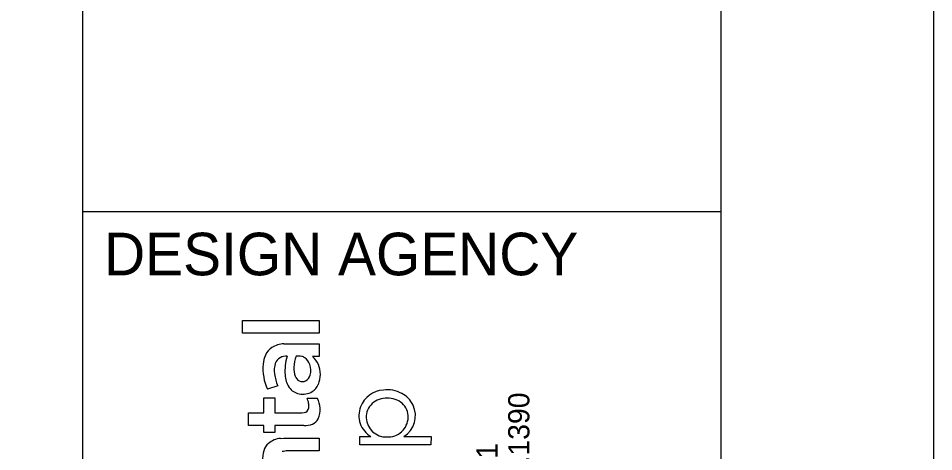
# Model space of a CAD drawing. Extents: x -0.4 to 34, y 0 to 22.
# Drawn here: x 31.848 to 34, y 3.936 to 4.953 of the extents above; entities that cross this region are included whole.
import ezdxf

# ---------------------------------------------------------------- set-up
doc = ezdxf.new("R2010")
doc.units = 0
for name, color, linetype in [('SH_Border', 7, 'Continuous'), ('SH_Cut_Line', 7, 'Continuous'), ('SH_Data', 7, 'Continuous')]:
    doc.layers.add(name, color=color, linetype=linetype)

msp = doc.modelspace()

# ---------------------------------------------------------------- linework, layer by layer
at = {"layer": 'SH_Border'}
for p, q in [((32, 0.5), (32, 21.5)), ((32, 4.5), (33.5, 4.5))]:
    msp.add_line(p, q, dxfattribs=at)
msp.add_lwpolyline([(1.5, 21.5), (33.5, 21.5), (33.5, 0.5), (1.5, 0.5)], close=True, dxfattribs=at)
at = {"layer": 'SH_Cut_Line'}
msp.add_lwpolyline([(0, 0), (34, 0), (34, 22), (0, 22)], close=True, dxfattribs=at)
at = {"layer": 'SH_Data'}
for p, q in [((32.3756, 4.2141), (32.3756, 4.244)), ((32.3756, 4.244), (32.5557, 4.244)), ((32.5557, 4.244), (32.5557, 4.2141)), ((32.5557, 4.2141), (32.3756, 4.2141)), ((32.4727, 4.189), (32.5555, 4.1892)), ((32.5555, 4.1892), (32.5557, 4.1596)), ((32.5557, 4.1596), (32.5397, 4.1596)), ((32.4582, 4.0904), (32.4343, 4.0823)), ((32.4254, 4.027), (32.4255, 4.0621)), ((32.4255, 4.0621), (32.4511, 4.0621)), ((32.4511, 4.0621), (32.4512, 4.027)), ((32.527, 4.0616), (32.5511, 4.0616)), ((32.3896, 3.9972), (32.3896, 4.027)), ((32.3896, 4.027), (32.4254, 4.027)), ((32.4512, 4.027), (32.515, 4.027)), ((32.515, 4.027), (32.52, 4.0275)), ((32.4254, 3.9972), (32.3896, 3.9972)), ((32.4254, 3.9807), (32.4254, 3.9972)), ((32.4511, 3.9807), (32.4254, 3.9807)), ((32.5197, 3.9972), (32.4511, 3.9972)), ((32.4511, 3.9972), (32.4511, 3.9807)), ((32.4644, 3.9669), (32.4729, 3.9673)), ((32.4729, 3.9673), (32.5557, 3.9673)), ((32.5557, 3.9673), (32.5557, 3.9375)), ((32.6515, 3.9521), (32.6515, 3.9711)), ((32.6515, 3.9711), (32.6771, 3.9711)), ((32.7549, 3.9713), (32.8186, 3.9711)), ((32.8186, 3.9711), (32.8184, 3.9521)), ((32.5557, 3.9375), (32.4814, 3.9375)), ((32.8184, 3.9521), (32.6515, 3.9521))]:
    msp.add_line(p, q, dxfattribs=at)
msp.add_lwpolyline([(32.3756, 4.2141), (32.3756, 4.244), (32.5557, 4.244), (32.5557, 4.2141)], close=True, dxfattribs=at)
for points in [[(32.4727, 4.189), (32.5555, 4.1892), (32.5557, 4.1596)], [(32.5557, 4.1596), (32.5397, 4.1596)], [(32.4582, 4.0904), (32.4343, 4.0823)], [(32.5197, 3.9972), (32.4511, 3.9972), (32.4511, 3.9807), (32.4254, 3.9807), (32.4254, 3.9972), (32.3896, 3.9972), (32.3896, 4.027), (32.4254, 4.027), (32.4255, 4.0621), (32.4511, 4.0621), (32.4512, 4.027), (32.515, 4.027), (32.52, 4.0275)], [(32.527, 4.0616), (32.5511, 4.0616)], [(32.4644, 3.9669), (32.4729, 3.9673), (32.5557, 3.9673), (32.5557, 3.9375), (32.4814, 3.9375)], [(32.7549, 3.9713), (32.8186, 3.9711), (32.8184, 3.9521), (32.6515, 3.9521)], [(32.6515, 3.9521), (32.6515, 3.9711), (32.6771, 3.9711)]]:
    msp.add_lwpolyline(points, dxfattribs=at)
for centre, radius, start, end in [((32.4685, 4.1447), 0.043, 124.537, 155.6594), ((32.4685, 4.1447), 0.043, 124.537, 155.6594), ((32.4745, 4.1326), 0.0565, 91.8942, 122.6317), ((32.4745, 4.1326), 0.0565, 91.8942, 122.6317), ((32.4882, 4.1361), 0.0646, 155.9764, 175.3149), ((32.4882, 4.1361), 0.0646, 155.9764, 175.3149), ((32.4753, 4.1356), 0.024, 119.4252, 161.6629), ((32.4753, 4.1356), 0.024, 119.4252, 161.6629), ((32.4779, 4.1278), 0.0321, 85.3802, 116.6222), ((32.4779, 4.1278), 0.0321, 85.3802, 116.6222), ((32.5879, 4.1251), 0.1129, 162.0821, 184.5285), ((32.5879, 4.1251), 0.1129, 162.0821, 184.5285), ((32.5801, 4.1313), 0.0841, 159.8366, 178.0362), ((32.5801, 4.1313), 0.0841, 159.8366, 178.0362), ((32.5051, 4.1074), 0.053, 79.6696, 94.2322), ((32.5051, 4.1074), 0.053, 79.6696, 94.2322), ((32.5089, 4.1364), 0.0238, 56.8913, 76.2149), ((32.5089, 4.1364), 0.0238, 56.8913, 76.2149), ((32.5052, 4.1318), 0.0297, 17.5984, 55.7282), ((32.5052, 4.1318), 0.0297, 17.5984, 55.7282), ((32.5055, 4.1191), 0.0529, 358.0746, 49.762), ((32.5055, 4.1191), 0.0529, 358.0746, 49.762), ((32.5364, 4.1308), 0.113, 174.6101, 205.3899), ((32.5364, 4.1308), 0.113, 174.6101, 205.3899), ((32.5076, 4.1265), 0.0576, 163.1369, 188.1675), ((32.5076, 4.1265), 0.0576, 163.1369, 188.1675), ((32.5466, 4.1303), 0.0506, 175.5903, 199.8857), ((32.5466, 4.1303), 0.0506, 175.5903, 199.8857), ((32.4916, 4.1264), 0.0443, 345.9408, 18.9919), ((32.4916, 4.1264), 0.0443, 345.9408, 18.9919), ((32.5473, 4.1297), 0.0973, 186.7598, 203.7981), ((32.5473, 4.1297), 0.0973, 186.7598, 203.7981), ((32.5328, 4.1187), 0.0575, 182.5676, 213.7144), ((32.5328, 4.1187), 0.0575, 182.5676, 213.7144), ((32.5164, 4.1189), 0.0184, 198.2844, 293.3081), ((32.5164, 4.1189), 0.0184, 198.2844, 293.3081), ((32.5152, 4.1199), 0.0199, 295.2883, 347.4639), ((32.5152, 4.1199), 0.0199, 295.2883, 347.4639), ((32.5019, 4.1168), 0.0566, 336.016, 0.5951), ((32.5019, 4.1168), 0.0566, 336.016, 0.5951), ((32.5175, 4.1097), 0.0394, 303.4436, 336.18), ((32.5175, 4.1097), 0.0394, 303.4436, 336.18), ((32.5149, 4.1078), 0.0366, 215.0668, 259.8133), ((32.5149, 4.1078), 0.0366, 215.0668, 259.8133), ((32.5175, 4.1131), 0.0423, 257.5256, 300.882), ((32.5175, 4.1131), 0.0423, 257.5256, 300.882), ((32.7108, 4.0182), 0.0624, 93.9866, 158.3119), ((32.7108, 4.0182), 0.0624, 93.9866, 158.3119), ((32.7156, 4.0065), 0.0746, 62.6889, 97.0135), ((32.7156, 4.0065), 0.0746, 62.6889, 97.0135), ((32.7212, 4.0191), 0.0608, 25.0657, 61.9602), ((32.7212, 4.0191), 0.0608, 25.0657, 61.9602), ((32.4863, 4.042), 0.0452, 10.1545, 25.723), ((32.4863, 4.042), 0.0452, 10.1545, 25.723), ((32.4957, 4.0436), 0.0356, 351.914, 10.2059), ((32.4957, 4.0436), 0.0356, 351.914, 10.2059), ((32.503, 4.0351), 0.0549, 336.589, 28.8991), ((32.503, 4.0351), 0.0549, 336.589, 28.8991), ((32.7092, 4.0167), 0.0434, 132.3289, 182.0949), ((32.7092, 4.0167), 0.0434, 132.3289, 182.0949), ((32.7138, 4.0102), 0.0513, 87.8965, 131.1812), ((32.7138, 4.0102), 0.0513, 87.8965, 131.1812), ((32.7175, 4.0102), 0.0513, 49.9089, 92.0363), ((32.7175, 4.0102), 0.0513, 49.9089, 92.0363), ((32.7215, 4.0173), 0.0433, 358.0487, 47.9447), ((32.7215, 4.0173), 0.0433, 358.0487, 47.9447), ((32.5184, 4.04), 0.0126, 277.6142, 353.7918), ((32.5184, 4.04), 0.0126, 277.6142, 353.7918), ((32.707, 4.0202), 0.0581, 158.656, 198.171), ((32.707, 4.0202), 0.0581, 158.656, 198.171), ((32.7245, 4.02), 0.0574, 301.9776, 25.6418), ((32.7245, 4.02), 0.0574, 301.9776, 25.6418), ((32.5291, 4.0261), 0.0275, 292.6889, 332.0598), ((32.5291, 4.0261), 0.0275, 292.6889, 332.0598), ((32.7103, 4.0243), 0.0627, 200.8399, 238.0162), ((32.7103, 4.0243), 0.0627, 200.8399, 238.0162), ((32.7135, 4.0181), 0.0478, 183.5974, 271.7045), ((32.7135, 4.0181), 0.0478, 183.5974, 271.7045), ((32.7172, 4.018), 0.0477, 267.3149, 357.4019), ((32.7172, 4.018), 0.0477, 267.3149, 357.4019), ((32.5209, 4.0486), 0.0514, 268.6727, 291.5235), ((32.5209, 4.0486), 0.0514, 268.6727, 291.5235), ((32.4687, 3.9172), 0.0499, 94.9706, 130.2248), ((32.4687, 3.9172), 0.0499, 94.9706, 130.2248), ((32.4787, 3.9211), 0.056, 162.274, 187.7917), ((32.4787, 3.9211), 0.056, 162.274, 187.7917), ((32.4635, 3.9255), 0.0402, 132.2238, 161.6823), ((32.4635, 3.9255), 0.0402, 132.2238, 161.6823), ((32.4811, 3.8915), 0.046, 89.6051, 105.3303), ((32.4811, 3.8915), 0.046, 89.6051, 105.3303)]:
    msp.add_arc(centre, radius, start, end, dxfattribs=at)

# ---------------------------------------------------------------- texts
msp.add_text('DESIGN AGENCY', height=0.1, dxfattribs=at).set_placement((32.05, 4.35))
for s, p in [('800.835.1390', (33.0497, 3.6671)), ('450 GRANT ST., AKRON, OH  44311', (32.9749, 2.8374))]:
    msp.add_text(s, height=0.049846, rotation=90, dxfattribs=at).set_placement(p)

doc.saveas('drawing.dxf')
